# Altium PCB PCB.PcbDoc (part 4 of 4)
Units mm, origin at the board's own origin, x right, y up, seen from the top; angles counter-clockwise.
Board outline 430 x 130 mm, 2 copper layers (Top Layer, Bottom Layer); 471 components, 267 nets, 1806 pads, 471 vias.
Unrouted connection lines stored in the file: 127.
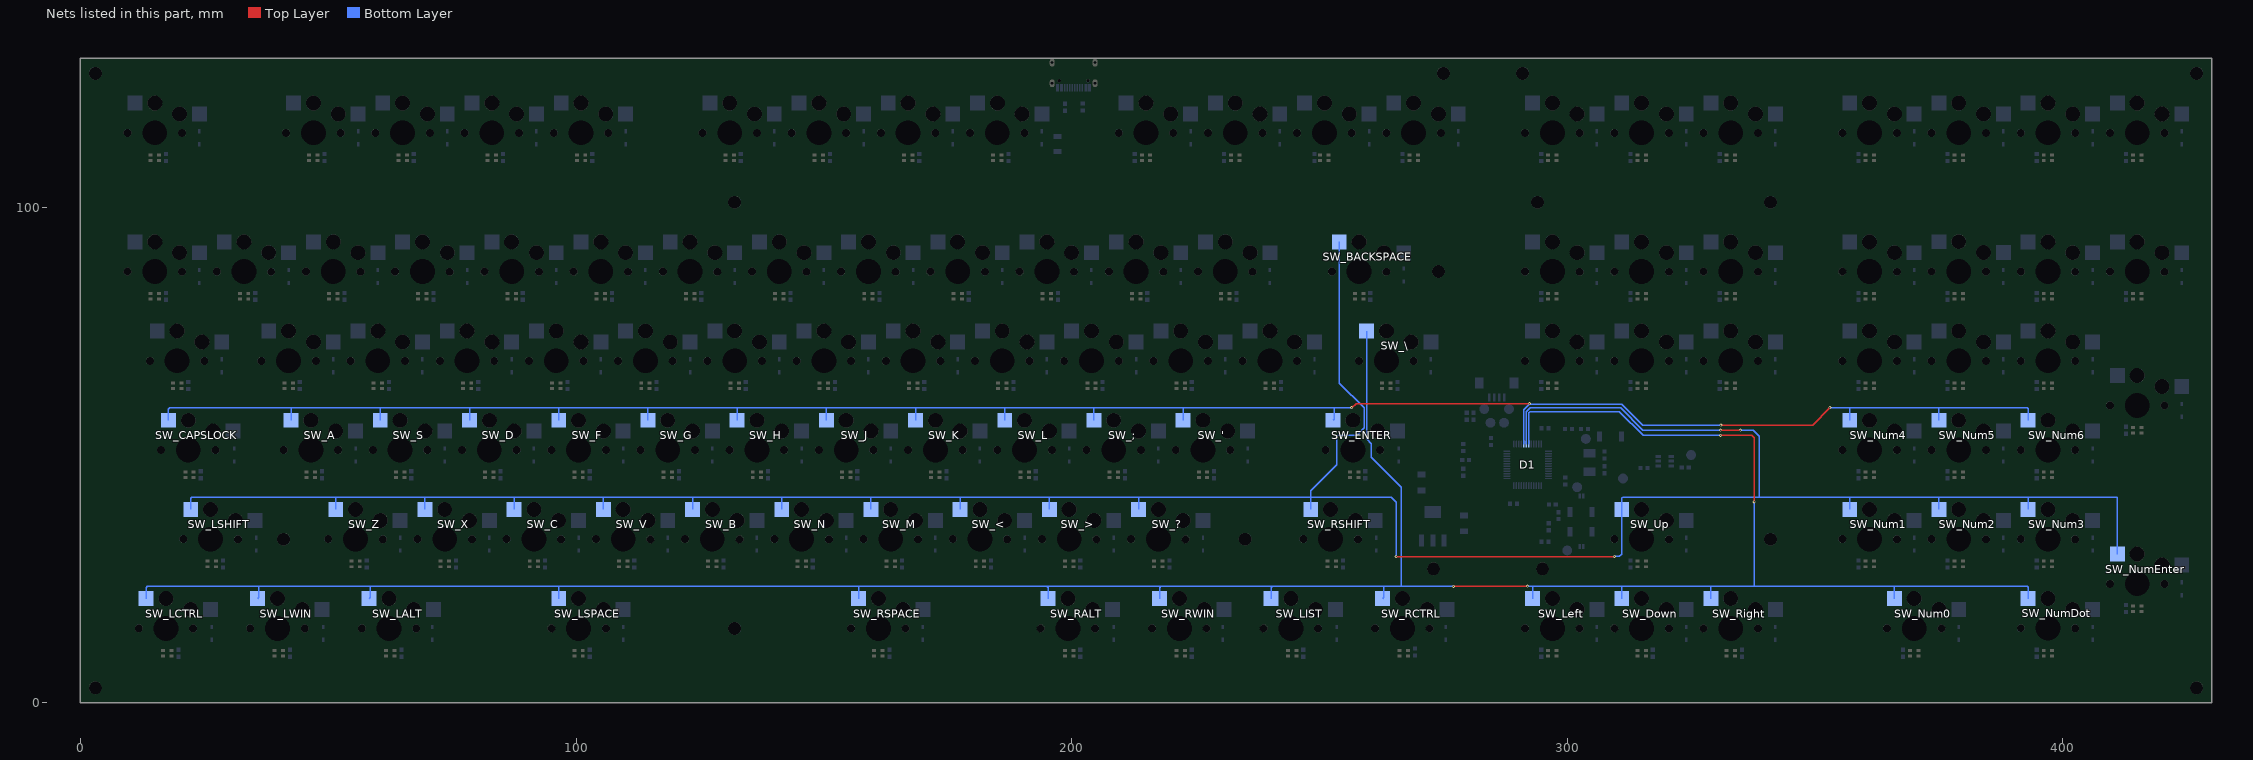
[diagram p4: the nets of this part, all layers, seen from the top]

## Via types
v1: diameter 0.6, hole 0.3, Top Layer to Bottom Layer, tented both sides, 471 vias

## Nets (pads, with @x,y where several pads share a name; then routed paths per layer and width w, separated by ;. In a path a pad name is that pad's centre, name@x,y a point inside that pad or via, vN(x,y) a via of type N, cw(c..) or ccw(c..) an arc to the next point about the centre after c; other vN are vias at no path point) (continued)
Row_4: D1.41 SW_'.2 SW_;.2 SW_A.2 SW_CAPSLOCK.2 SW_D.2 SW_ENTER.2 SW_F.2 SW_G.2 SW_H.2 SW_J.2 SW_K.2 SW_L.2 SW_Num4.2 SW_Num5.2 SW_Num6.2 SW_S.2 | length 427.4
  Top Layer w0.254: v1(256.491,59.536) 256.564,59.536 257.402,60.375 v1(292.375,60.375) ; v1(330.991,56.036) 349.536,56.036 v1@353,59.5
  Bottom Layer w0.254: SW_CAPSLOCK.2@17.75,57 17.75,59.25 18,59.5 42.5,59.5 ; SW_A.2@42.5,57 42.5,59.5 ; SW_S.2@60.5,57 60.5,59.5 ; SW_D.2@78.5,57 78.5,59.5 ; SW_F.2@96.5,57 96.5,59.5 ; SW_G.2@114.5,57 114.5,59.5 ; SW_H.2@132.5,57 132.5,59.5 ; SW_J.2@150.5,57 150.5,59.5 ; SW_K.2@168.5,57 168.5,59.5 ; SW_L.2@186.5,57 186.5,59.5 ; 204.5,57 204.5,59.5 ; SW_'.2@222.5,57 222.5,59.5 ; SW_ENTER.2@252.75,57 253,57.25 253,59.351 252.851,59.5 ; v1@256.5,59.5 252.851,59.5 ; D1.41@291.25,52.2 291.25,59.125 292.21,60.085 292.21,60.116 292.344,60.25 v1@292.375,60.25 ; v1(292.375,60.375) 292.422,60.328 292.5,60.25 311,60.25 315.25,56 v1@331,56 ; v1(352.991,59.536) 353.027,59.5 357.149,59.5 ; SW_Num4.2@357,57 357,59.351 357.149,59.5 ; SW_Num5.2@375,57 375,59.5 ; SW_Num6.2@393,57 393,59.351 392.851,59.5 375,59.5 ; 42.5,59.5 60.5,59.5 ; 60.5,59.5 78.5,59.5 ; 78.5,59.5 96.5,59.5 ; 96.5,59.5 114.5,59.5 ; 114.5,59.5 132.5,59.5 ; 132.5,59.5 150.5,59.5 ; 150.5,59.5 168.5,59.5 ; 168.5,59.5 186.5,59.5 ; 186.5,59.5 204.5,59.5 ; 204.5,59.5 222.5,59.5 ; 222.5,59.5 252.851,59.5 ; 357.149,59.5 375,59.5
Row_5: D1.42 SW_<.2 SW_>.2 SW_?.2 SW_B.2 SW_BACKSPACE.2 SW_C.2 SW_LSHIFT.2 SW_M.2 SW_N.2 SW_Num1.2 SW_Num2.2 SW_Num3.2 SW_NumEnter.2 SW_RSHIFT.2 SW_Up.2 SW_V.2 SW_X.2 SW_Z.2 | length 589.4
  Top Layer w0.254: v1(265.491,29.536) 265.527,29.5 v1@309.5,29.5 ; v1@331,55 334.944,55 v1(334.953,55.009)
  Bottom Layer w0.254: SW_LSHIFT.2@22.25,39 22.25,41.25 22.5,41.5 51.5,41.5 ; SW_Z.2@51.5,39 51.5,41.5 ; SW_X.2@69.5,39 69.5,41.5 ; SW_C.2@87.5,39 87.5,41.5 ; SW_V.2@105.5,39 105.5,41.5 ; SW_B.2@123.5,39 123.5,41.5 ; SW_N.2@141.5,39 141.5,41.5 ; SW_M.2@159.5,39 159.5,41.5 ; SW_<.2@177.5,39 177.5,41.5 ; SW_>.2@195.5,39 195.5,41.5 ; SW_?.2@213.5,39 213.5,41.5 ; SW_RSHIFT.2@248.25,39 248.25,41.5 ; SW_BACKSPACE.2@254,93 254,64.5 259,59.5 259,55.5 257.5,54 253.649,54 253.5,53.851 253.5,48 248.25,42.75 248.25,41.5 ; v1@265.5,29.5 265.5,40.5 264.5,41.5 248.25,41.5 ; D1.42@291.75,52.2 291.75,58.75 292.5,59.5 310.75,59.5 315.241,55.009 v1(330.953,55.009) ; v1(309.491,29.536) 310.536,29.536 311,30 SW_Up.2@311,39 311,41.351 311.149,41.5 338.75,41.5 ; v1(334.953,55.009) 337.491,55.009 338.75,53.75 338.75,41.5 ; SW_Num1.2@357,39 357,41.351 357.149,41.5 ; SW_Num2.2@375,39 375,41.5 ; SW_Num3.2@393,39 393,41.351 393.149,41.5 ; SW_NumEnter.2@411,30 411,41.351 410.851,41.5 393.149,41.5 ; 51.5,41.5 69.5,41.5 ; 69.5,41.5 87.5,41.5 ; 87.5,41.5 105.5,41.5 ; 105.5,41.5 123.5,41.5 ; 123.5,41.5 141.5,41.5 ; 141.5,41.5 159.5,41.5 ; 159.5,41.5 177.5,41.5 ; 177.5,41.5 195.5,41.5 ; 195.5,41.5 213.5,41.5 ; 213.5,41.5 248.25,41.5 ; 338.75,41.5 357.149,41.5 ; 357.149,41.5 375,41.5 ; 375,41.5 393.149,41.5
Row_6: D1.43 SW_\.2 SW_Down.2 SW_LALT.2 SW_LCTRL.2 SW_Left.2 SW_LIST.2 SW_LSPACE.2 SW_LWIN.2 SW_Num0.2 SW_NumDot.2 SW_RALT.2 SW_RCTRL.2 SW_Right.2 SW_RSPACE.2 SW_RWIN.2 | length 553.7
  Top Layer w0.254: v1(277,23.5) 291.954,23.5 v1(291.991,23.536) ; v1@331,54 337.25,54 337.75,53.5 337.75,40.556 v1(337.703,40.509)
  Bottom Layer w0.254: SW_LCTRL.2@13.25,21 13.25,23.246 13.504,23.5 36,23.5 ; SW_LWIN.2@35.75,21 36,21.25 36,23.5 ; SW_LALT.2@58.25,21 58.5,21.25 58.5,23.5 ; SW_LSPACE.2@96.5,21 96.5,23.5 ; SW_RSPACE.2@157,21 157,23.5 ; SW_RALT.2@195.25,21 195.25,23.25 195,23.5 ; SW_RWIN.2@217.75,21 217.75,23.25 218,23.5 ; SW_LIST.2@240.25,21 240.25,23.25 240.5,23.5 ; SW_\.2@259.5,75 259.5,53.25 260.5,52.25 260.5,49.5 266.5,43.5 266.5,23.536 266.536,23.5 ; SW_RCTRL.2@262.75,21 263,21.25 263,23.5 ; v1(277,23.5) 266.536,23.5 ; v1(291.991,23.536) 292.027,23.5 293.149,23.5 ; D1.43@292.25,52.2 292.25,58.5 292.5,58.75 310.5,58.75 315.292,53.958 v1(330.936,53.958) ; SW_Left.2@293,21 293,23.351 293.149,23.5 ; SW_Down.2@311,21 311,23.5 ; SW_Right.2@329,21 329,23.5 ; v1@337.75,40.5 337.75,23.5 ; SW_Num0.2@366,21 366,23.5 ; SW_NumDot.2@393.003,21.029 393.003,23.351 392.854,23.5 366,23.5 ; 36,23.5 58.5,23.5 ; 58.5,23.5 96.5,23.5 ; 96.5,23.5 157,23.5 ; 157,23.5 195,23.5 ; 195,23.5 218,23.5 ; 218,23.5 240.5,23.5 ; 240.5,23.5 263,23.5 ; 263,23.5 266.536,23.5 ; 293.149,23.5 311,23.5 ; 311,23.5 329,23.5 ; 329,23.5 337.75,23.5 ; 337.75,23.5 366,23.5
pads on no net: D1. D1.1 D1.2 D1.3 D1.4 D2. D3. D_F12.1 SW_0.5 SW_1.5 SW_2.5 SW_3.5 SW_4.5 SW_5.5 SW_6.5 SW_7.5 SW_8.5 SW_9.5 SW_'.5 SW_+.5 SW_-.5 SW_;.5 SW_<.5 SW_>.5 SW_?.5 SW_[.5 SW_\.5 SW_].5 SW_A.5 SW_B.5 SW_BACKSPACE.5 SW_C.5 SW_CAPSLOCK.5 SW_D.5 SW_Delete.5 SW_Down.5 SW_E.5 SW_End.5 SW_ENTER.5 SW_ESC.5 SW_F1.5 SW_F2.5 SW_F3.5 SW_F4.5 SW_F5.5 SW_F6.5 SW_F7.5 SW_F8.5 SW_F9.5 SW_F10.5 SW_F11.5 SW_F12.5 SW_F.5 SW_G.5 SW_H.5 SW_Home.5 SW_I.5 SW_Insert.5 SW_J.5 SW_K.5 SW_L.5 SW_LALT.5 SW_LCTRL.5 SW_Left.5 SW_LIST.5 SW_LSHIFT.5 SW_LSPACE.5 SW_LWIN.5 SW_M.5 SW_MUTE.5 SW_N.5 SW_Num0.5 SW_Num1.5 SW_Num2.5 SW_Num3.5 SW_Num4.5 SW_Num5.5 SW_Num6.5 SW_Num7.5 SW_Num8.5 SW_Num9.5 SW_Num*.5 SW_Num+.5 SW_Num-.5 SW_Num/.5 SW_NumDot.5 SW_NumEnter.5 SW_NumLock.5 SW_O.5 SW_P.5 SW_PageDown.5 SW_PageUp.5 SW_PauseBreak.5 SW_PLAY.5 SW_PrintScreen.5 SW_Q.5 SW_R.5 SW_RALT.5 SW_RCTRL.5 SW_Right.5 SW_RSHIFT.5 SW_RSPACE.5 SW_RWIN.5 SW_S.5 SW_ScrollLock.5 SW_T.5 SW_TAB.5 SW_U.5 SW_Up.5 SW_V.5 SW_VOL+.5 SW_VOL_-.5 SW_W.5 SW_X.5 SW_Y.5 SW_Z.5 SW_~.5 X1.2 X1.A8 X1.B8 X2. X2.0

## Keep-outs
Keep-Out Layer:
  the board outline again, w0.254

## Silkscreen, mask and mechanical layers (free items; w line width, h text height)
Top Overlay:
  lines w0.2: 100.5,24 100.5,29.2
  lines w0.254: 6,96 6,6 28.5,6 ; 51,24 51,6 ; 73.5,24 73.5,6 ; 188,24 188,6 ; 210.5,24 210.5,6 ; 233,24 233,6 ; 240,78 278,78 278,96 ; 240,96 278,96 ; 255.5,24 255.5,6 ; 6,42 46.5,42 46.5,24 6,24 28.5,24 28.5,6 ; 6,42 6,60 ; 6,42 37.5,42 37.5,60 6,60 ; 6,60 33,60 33,78 6,78 6,60 ; 28.5,6 51,6 ; 51,6 73.5,6 ; 73.5,6 188,6 ; 188,6 210.5,6 ; 210.5,6 233,6 ; 233,6 255.5,6 ; 255.5,6 278,6 278,96
  text "by LitLageR" at 406,3.405 h2
  text "04.07.2022" at 415,3.373 h2
Bottom Overlay:
  text "RESET" at 302.496,52.754 h1
  text "DATA_LED_5" at 336.246,49.421 h1
  text "DATA_LED_3.3" at 324.246,44.671 h1
  text "BOOT_0" at 308.996,42.921 h1
  text "BOOT_1" at 298.496,30.171 h1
